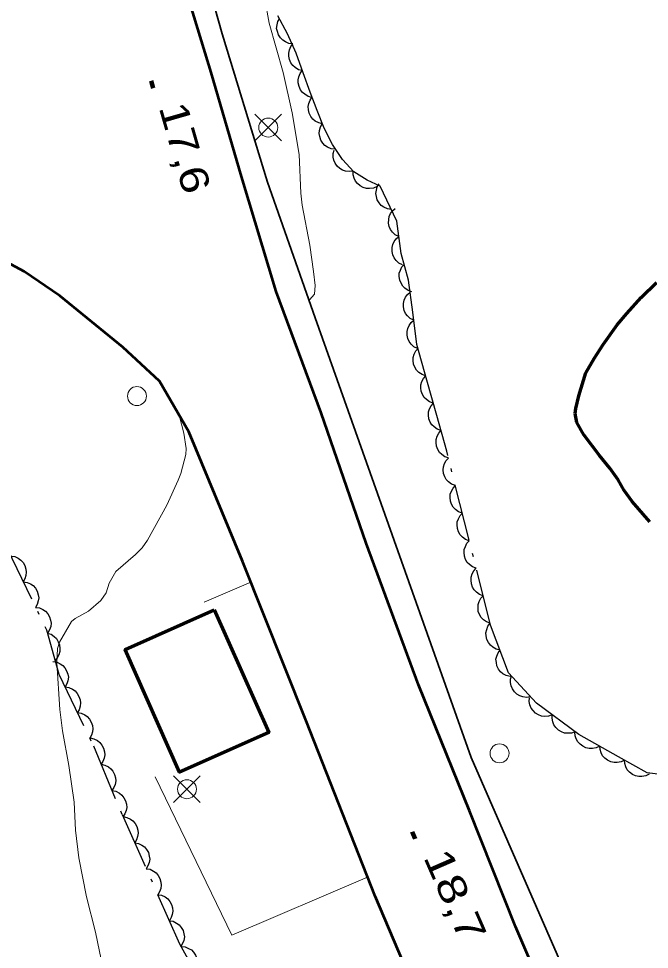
# Model space of a CAD drawing. Extents: x 355726 to 357533, y 5103782 to 5105258.
# Drawn here: x 356339.71 to 356372.99, y 5104791.53 to 5104840.63 of the extents above; entities that cross this region are included whole.
import ezdxf

# ---------------------------------------------------------------- set-up
doc = ezdxf.new("R2010")
doc.units = 0
doc.header["$LTSCALE"] = 0.6
doc.linetypes.add('DOT_DASHED', pattern=[7.7, 5, -1.2, 0.3, -1.2])
doc.linetypes.add('LONG_DASHED', pattern=[7.5, 6, -1.5])
for name, color, linetype, lineweight in [('19', 7, 'Continuous', 13), ('2', 7, 'LONG_DASHED', 13), ('21', 7, 'LONG_DASHED', 35), ('22', 7, 'Continuous', 13), ('3', 7, 'Continuous', 140), ('31', 7, 'Continuous', 35), ('36', 7, 'Continuous', 13), ('44', 7, 'Continuous', 25)]:
    doc.layers.add(name, color=color, linetype=linetype, lineweight=lineweight)

msp = doc.modelspace()

# ---------------------------------------------------------------- linework, layer by layer
at = {"layer": '19'}
msp.add_line((356351.97, 5104810.9), (356349.5, 5104809.84), dxfattribs=at)
msp.add_lwpolyline([(356346.92, 5104800.63), (356350.96, 5104792.28), (356358.13, 5104795.33)], dxfattribs=at)
at = {"layer": '2', "linetype": 'Continuous'}
for points in [[(356355.04, 5104825.77), (356355.07, 5104825.79), (356355.33, 5104826.09), (356355.37, 5104826.55), (356355.28, 5104827.3), (356355.08, 5104828.68), (356354.68, 5104830.8), (356354.6, 5104831.42), (356354.51, 5104833.46), (356354.14, 5104835.66), (356353.67, 5104837.8), (356352.94, 5104840.4), (356352.7, 5104841.67)], [(356344.33, 5104810.34), (356344.5, 5104810.84), (356344.85, 5104811.47), (356345.89, 5104812.36), (356346.23, 5104812.72), (356346.52, 5104813.12), (356347.54, 5104814.96), (356348.13, 5104816.28), (356348.27, 5104816.63), (356348.53, 5104817.63), (356348.56, 5104817.95), (356348.44, 5104818.76), (356348.19, 5104819.71)]]:
    msp.add_lwpolyline(points, dxfattribs=at)
at = {"layer": '2'}
msp.add_lwpolyline([(356344.17, 5104790.49), (356343.78, 5104792.43), (356343.29, 5104794.3), (356342.89, 5104796.36), (356342.72, 5104797.82), (356342.64, 5104799.29), (356342.37, 5104801.23), (356342.03, 5104803.05), (356341.89, 5104804.18), (356341.73, 5104806.65), (356341.77, 5104807.4), (356341.88, 5104807.74), (356342.5, 5104808.82), (356342.7, 5104808.98), (356343.41, 5104809.37), (356344.06, 5104809.93), (356344.33, 5104810.34)], dxfattribs=at)
at = {"layer": '21', "linetype": 'Continuous', "lineweight": 53}
for points in [[(356404.43, 5104711.57), (356400.53, 5104719.2), (356396.79, 5104726.53), (356393.27, 5104733.76), (356389.5, 5104741.82), (356385.15, 5104750.63), (356381.56, 5104758.3), (356377.92, 5104765.58), (356374.7, 5104772.49), (356371.83, 5104779.33), (356369.06, 5104785.41), (356365.93, 5104792.73), (356363.5, 5104798.84), (356360.81, 5104805.48), (356358.05, 5104812.95), (356355.68, 5104819.84), (356353.31, 5104826.24), (356351.48, 5104832.3), (356349.87, 5104837.8), (356347.69, 5104844.95), (356345.93, 5104851.12), (356344.93, 5104854.88), (356343.69, 5104859.4)], [(356399.2, 5104708.25), (356395.34, 5104715.51), (356391.68, 5104722.78), (356387.44, 5104731.3), (356383.54, 5104739.59), (356379.77, 5104747.55), (356376.2, 5104754.88), (356372.76, 5104762.24), (356368.76, 5104770.76), (356365.14, 5104778.76), (356362.28, 5104785.51), (356358.52, 5104794.34), (356354.89, 5104803.59), (356351.53, 5104812), (356348.69, 5104818.84), (356347.14, 5104821.51), (356345.22, 5104823.3), (356341.89, 5104826.01), (356340, 5104827.3), (356337.89, 5104828.42)]]:
    msp.add_lwpolyline(points, dxfattribs=at)
at = {"layer": '22', "lineweight": 35}
msp.add_lwpolyline([(356343.73, 5104859.46), (356345.26, 5104859.67), (356346.18, 5104855.37), (356348.16, 5104847.95), (356350.45, 5104839.83), (356352.85, 5104832.01), (356355.37, 5104824.84), (356363.6, 5104801.65), (356370.06, 5104786.82), (356377.26, 5104770.55), (356384.15, 5104755.63), (356392.22, 5104739.09), (356398.99, 5104725.29), (356406.44, 5104710.76)], dxfattribs=at)
at = {"layer": '22', "linetype": 'LONG_DASHED', "lineweight": 70}
msp.add_lwpolyline([(356373.02, 5104814.09), (356372.09, 5104815.15), (356371.66, 5104815.74), (356371.35, 5104816.3), (356370.91, 5104816.92), (356370.36, 5104817.59), (356369.53, 5104818.68), (356369.17, 5104819.33), (356369.08, 5104819.8), (356369.11, 5104820.07), (356369.27, 5104820.74), (356369.65, 5104821.95), (356370.08, 5104822.7), (356370.56, 5104823.44), (356371.3, 5104824.48), (356371.8, 5104825.08), (356372.57, 5104825.92), (356373.37, 5104826.72)], dxfattribs=at)
at = {"layer": '3'}
for p, q in [((356346.71, 5104837.35), (356346.82, 5104836.97)), ((356360.48, 5104797.72), (356360.64, 5104797.36))]:
    msp.add_line(p, q, dxfattribs=at)
at = {"layer": '31', "lineweight": 70}
msp.add_lwpolyline([(356350.03, 5104809.44), (356352.91, 5104802.97), (356348.21, 5104800.88), (356345.33, 5104807.34), (356350.03, 5104809.44)], close=True, dxfattribs=at)
at = {"layer": '36'}
for p, q in [((356353.59, 5104834.18), (356352.18, 5104835.59)), ((356352.18, 5104834.18), (356353.59, 5104835.59)), ((356349.3, 5104799.27), (356347.89, 5104800.68)), ((356347.89, 5104799.27), (356349.3, 5104800.68))]:
    msp.add_line(p, q, dxfattribs=at)
for centre in [(356352.887, 5104834.887), (356345.959, 5104820.72), (356365.089, 5104801.87), (356348.597, 5104799.977)]:
    msp.add_circle(centre, 0.5, dxfattribs=at)
at = {"layer": '44'}
for points in [[(356354.19, 5104839.31), (356353.98, 5104839.33), (356353.79, 5104839.41), (356353.65, 5104839.5), (356353.53, 5104839.62), (356353.43, 5104839.78), (356353.37, 5104839.96), (356353.33, 5104840.12), (356353.35, 5104840.3), (356353.4, 5104840.48), (356353.48, 5104840.63)], [(356354.68, 5104837.89), (356354.48, 5104837.94), (356354.31, 5104838.05), (356354.18, 5104838.16), (356354.08, 5104838.3), (356354.01, 5104838.47), (356353.97, 5104838.66), (356353.97, 5104838.82), (356354.01, 5104838.99), (356354.08, 5104839.16), (356354.19, 5104839.31)], [(356355.19, 5104836.48), (356354.99, 5104836.53), (356354.81, 5104836.64), (356354.69, 5104836.74), (356354.59, 5104836.88), (356354.51, 5104837.05), (356354.47, 5104837.24), (356354.46, 5104837.4), (356354.5, 5104837.57), (356354.57, 5104837.74), (356354.68, 5104837.89)], [(356355.75, 5104835.09), (356355.55, 5104835.13), (356355.37, 5104835.23), (356355.24, 5104835.33), (356355.13, 5104835.47), (356355.05, 5104835.64), (356355.01, 5104835.82), (356354.99, 5104835.99), (356355.03, 5104836.16), (356355.09, 5104836.33), (356355.19, 5104836.48)], [(356356.41, 5104833.74), (356356.2, 5104833.77), (356356.02, 5104833.85), (356355.88, 5104833.94), (356355.76, 5104834.07), (356355.66, 5104834.22), (356355.6, 5104834.41), (356355.57, 5104834.57), (356355.59, 5104834.74), (356355.64, 5104834.92), (356355.73, 5104835.08)], [(356357.37, 5104832.59), (356357.17, 5104832.56), (356356.96, 5104832.59), (356356.81, 5104832.63), (356356.66, 5104832.73), (356356.52, 5104832.85), (356356.42, 5104833.01), (356356.34, 5104833.16), (356356.31, 5104833.33), (356356.31, 5104833.52), (356356.36, 5104833.69)], [(356358.63, 5104831.77), (356358.44, 5104831.69), (356358.23, 5104831.67), (356358.07, 5104831.67), (356357.9, 5104831.72), (356357.74, 5104831.81), (356357.6, 5104831.94), (356357.49, 5104832.06), (356357.42, 5104832.22), (356357.37, 5104832.4), (356357.36, 5104832.58)], [(356359.38, 5104830.56), (356359.17, 5104830.59), (356358.99, 5104830.68), (356358.85, 5104830.77), (356358.74, 5104830.91), (356358.64, 5104831.07), (356358.59, 5104831.25), (356358.56, 5104831.41), (356358.59, 5104831.59), (356358.64, 5104831.76), (356358.73, 5104831.92)], [(356359.78, 5104829.14), (356359.59, 5104829.23), (356359.44, 5104829.37), (356359.34, 5104829.5), (356359.27, 5104829.66), (356359.23, 5104829.84), (356359.24, 5104830.03), (356359.26, 5104830.19), (356359.34, 5104830.35), (356359.45, 5104830.5), (356359.58, 5104830.62)], [(356359.97, 5104827.65), (356359.78, 5104827.74), (356359.63, 5104827.88), (356359.53, 5104828.01), (356359.46, 5104828.17), (356359.42, 5104828.35), (356359.43, 5104828.55), (356359.46, 5104828.71), (356359.53, 5104828.87), (356359.64, 5104829.02), (356359.78, 5104829.14)], [(356360.47, 5104826.22), (356360.27, 5104826.29), (356360.1, 5104826.41), (356359.98, 5104826.52), (356359.89, 5104826.67), (356359.82, 5104826.84), (356359.8, 5104827.03), (356359.8, 5104827.2), (356359.86, 5104827.36), (356359.94, 5104827.53), (356360.06, 5104827.67)], [(356360.56, 5104824.72), (356360.38, 5104824.81), (356360.23, 5104824.95), (356360.13, 5104825.08), (356360.06, 5104825.24), (356360.02, 5104825.42), (356360.03, 5104825.61), (356360.05, 5104825.78), (356360.13, 5104825.93), (356360.24, 5104826.08), (356360.37, 5104826.2)], [(356360.76, 5104823.23), (356360.57, 5104823.32), (356360.42, 5104823.46), (356360.32, 5104823.59), (356360.25, 5104823.75), (356360.21, 5104823.93), (356360.22, 5104824.13), (356360.25, 5104824.29), (356360.32, 5104824.45), (356360.43, 5104824.6), (356360.56, 5104824.72)], [(356361.19, 5104821.79), (356361, 5104821.86), (356360.83, 5104821.97), (356360.71, 5104822.09), (356360.62, 5104822.24), (356360.55, 5104822.41), (356360.53, 5104822.6), (356360.53, 5104822.76), (356360.59, 5104822.93), (356360.67, 5104823.1), (356360.79, 5104823.23)], [(356361.6, 5104820.35), (356361.4, 5104820.41), (356361.23, 5104820.53), (356361.11, 5104820.64), (356361.02, 5104820.8), (356360.96, 5104820.97), (356360.94, 5104821.16), (356360.94, 5104821.32), (356360.99, 5104821.49), (356361.08, 5104821.65), (356361.2, 5104821.79)], [(356362, 5104818.9), (356361.8, 5104818.97), (356361.64, 5104819.09), (356361.52, 5104819.2), (356361.43, 5104819.35), (356361.36, 5104819.52), (356361.34, 5104819.71), (356361.34, 5104819.88), (356361.4, 5104820.04), (356361.48, 5104820.21), (356361.6, 5104820.35)], [(356362.4, 5104817.46), (356362.2, 5104817.52), (356362.04, 5104817.64), (356361.92, 5104817.75), (356361.83, 5104817.9), (356361.76, 5104818.08), (356361.74, 5104818.27), (356361.74, 5104818.43), (356361.8, 5104818.6), (356361.88, 5104818.76), (356362, 5104818.9)], [(356362.76, 5104816), (356362.56, 5104816.07), (356362.4, 5104816.19), (356362.28, 5104816.31), (356362.2, 5104816.46), (356362.14, 5104816.64), (356362.12, 5104816.83), (356362.13, 5104816.99), (356362.18, 5104817.16), (356362.27, 5104817.32), (356362.39, 5104817.45)], [(356363.13, 5104814.54), (356362.93, 5104814.62), (356362.77, 5104814.74), (356362.65, 5104814.85), (356362.56, 5104815.01), (356362.5, 5104815.18), (356362.49, 5104815.37), (356362.49, 5104815.54), (356362.55, 5104815.7), (356362.64, 5104815.86), (356362.76, 5104816)], [(356363.49, 5104813.09), (356363.3, 5104813.16), (356363.13, 5104813.28), (356363.02, 5104813.4), (356362.93, 5104813.55), (356362.87, 5104813.73), (356362.86, 5104813.92), (356362.86, 5104814.08), (356362.92, 5104814.25), (356363.01, 5104814.41), (356363.13, 5104814.54)], [(356363.86, 5104811.64), (356363.66, 5104811.71), (356363.5, 5104811.83), (356363.38, 5104811.94), (356363.3, 5104812.1), (356363.24, 5104812.27), (356363.22, 5104812.46), (356363.23, 5104812.63), (356363.29, 5104812.79), (356363.37, 5104812.96), (356363.49, 5104813.09)], [(356339.3, 5104812.28), (356339.51, 5104812.25), (356339.7, 5104812.16), (356339.83, 5104812.07), (356339.95, 5104811.94), (356340.04, 5104811.78), (356340.1, 5104811.59), (356340.12, 5104811.43), (356340.1, 5104811.26), (356340.05, 5104811.08), (356339.96, 5104810.92)], [(356364.23, 5104810.18), (356364.03, 5104810.25), (356363.87, 5104810.37), (356363.75, 5104810.49), (356363.67, 5104810.64), (356363.61, 5104810.82), (356363.59, 5104811.01), (356363.59, 5104811.17), (356363.65, 5104811.34), (356363.74, 5104811.5), (356363.86, 5104811.64)], [(356339.96, 5104810.92), (356340.16, 5104810.89), (356340.35, 5104810.81), (356340.49, 5104810.72), (356340.6, 5104810.58), (356340.69, 5104810.43), (356340.75, 5104810.24), (356340.78, 5104810.08), (356340.75, 5104809.91), (356340.7, 5104809.73), (356340.61, 5104809.57)], [(356364.6, 5104808.73), (356364.4, 5104808.8), (356364.24, 5104808.92), (356364.12, 5104809.04), (356364.03, 5104809.19), (356363.97, 5104809.36), (356363.96, 5104809.56), (356363.96, 5104809.72), (356364.02, 5104809.88), (356364.11, 5104810.05), (356364.23, 5104810.18)], [(356340.61, 5104809.57), (356340.82, 5104809.54), (356341, 5104809.46), (356341.14, 5104809.37), (356341.25, 5104809.23), (356341.35, 5104809.08), (356341.4, 5104808.89), (356341.43, 5104808.73), (356341.41, 5104808.56), (356341.35, 5104808.38), (356341.26, 5104808.22)], [(356365.12, 5104807.32), (356364.91, 5104807.37), (356364.74, 5104807.47), (356364.61, 5104807.57), (356364.5, 5104807.72), (356364.42, 5104807.88), (356364.39, 5104808.07), (356364.37, 5104808.23), (356364.41, 5104808.4), (356364.48, 5104808.58), (356364.58, 5104808.72)], [(356341.23, 5104808.21), (356341.43, 5104808.15), (356341.59, 5104808.03), (356341.72, 5104807.92), (356341.81, 5104807.76), (356341.87, 5104807.59), (356341.89, 5104807.4), (356341.89, 5104807.24), (356341.84, 5104807.07), (356341.75, 5104806.91), (356341.64, 5104806.77)], [(356365.65, 5104805.92), (356365.44, 5104805.97), (356365.27, 5104806.07), (356365.14, 5104806.17), (356365.03, 5104806.31), (356364.95, 5104806.48), (356364.92, 5104806.67), (356364.9, 5104806.83), (356364.94, 5104807), (356365.01, 5104807.17), (356365.12, 5104807.32)], [(356341.52, 5104806.72), (356341.72, 5104806.69), (356341.91, 5104806.6), (356342.05, 5104806.51), (356342.16, 5104806.38), (356342.25, 5104806.22), (356342.31, 5104806.04), (356342.34, 5104805.88), (356342.31, 5104805.7), (356342.26, 5104805.53), (356342.17, 5104805.37)], [(356366.73, 5104804.85), (356366.52, 5104804.82), (356366.32, 5104804.85), (356366.16, 5104804.9), (356366.01, 5104804.99), (356365.88, 5104805.12), (356365.77, 5104805.28), (356365.7, 5104805.43), (356365.67, 5104805.6), (356365.67, 5104805.79), (356365.72, 5104805.96)], [(356342.17, 5104805.37), (356342.37, 5104805.34), (356342.56, 5104805.25), (356342.7, 5104805.16), (356342.81, 5104805.03), (356342.9, 5104804.87), (356342.96, 5104804.69), (356342.98, 5104804.53), (356342.96, 5104804.35), (356342.91, 5104804.17), (356342.82, 5104804.02)], [(356367.87, 5104803.9), (356367.68, 5104803.83), (356367.47, 5104803.82), (356367.31, 5104803.83), (356367.15, 5104803.9), (356366.99, 5104803.99), (356366.86, 5104804.13), (356366.75, 5104804.26), (356366.69, 5104804.42), (356366.66, 5104804.61), (356366.67, 5104804.79)], [(356342.82, 5104804.02), (356343.02, 5104803.99), (356343.21, 5104803.9), (356343.34, 5104803.81), (356343.46, 5104803.68), (356343.55, 5104803.52), (356343.61, 5104803.33), (356343.63, 5104803.17), (356343.61, 5104803), (356343.56, 5104802.82), (356343.47, 5104802.67)], [(356369.08, 5104803.01), (356368.89, 5104802.94), (356368.68, 5104802.93), (356368.52, 5104802.94), (356368.35, 5104803.01), (356368.2, 5104803.1), (356368.06, 5104803.24), (356367.96, 5104803.37), (356367.9, 5104803.53), (356367.87, 5104803.72), (356367.87, 5104803.9)], [(356370.38, 5104802.25), (356370.19, 5104802.16), (356369.99, 5104802.12), (356369.82, 5104802.12), (356369.65, 5104802.16), (356369.48, 5104802.24), (356369.34, 5104802.36), (356369.22, 5104802.47), (356369.14, 5104802.63), (356369.08, 5104802.8), (356369.07, 5104802.98)], [(356343.49, 5104802.68), (356343.69, 5104802.63), (356343.87, 5104802.54), (356344, 5104802.44), (356344.11, 5104802.3), (356344.2, 5104802.14), (356344.24, 5104801.95), (356344.26, 5104801.79), (356344.23, 5104801.62), (356344.16, 5104801.44), (356344.07, 5104801.29)], [(356371.68, 5104801.51), (356371.5, 5104801.42), (356371.3, 5104801.39), (356371.13, 5104801.38), (356370.96, 5104801.42), (356370.79, 5104801.5), (356370.64, 5104801.62), (356370.53, 5104801.74), (356370.45, 5104801.89), (356370.39, 5104802.07), (356370.38, 5104802.25)], [(356372.99, 5104800.77), (356372.8, 5104800.68), (356372.6, 5104800.65), (356372.43, 5104800.64), (356372.26, 5104800.69), (356372.1, 5104800.76), (356371.95, 5104800.88), (356371.83, 5104801), (356371.75, 5104801.16), (356371.7, 5104801.33), (356371.68, 5104801.51)], [(356344.07, 5104801.29), (356344.27, 5104801.25), (356344.45, 5104801.15), (356344.58, 5104801.06), (356344.69, 5104800.92), (356344.78, 5104800.75), (356344.82, 5104800.57), (356344.84, 5104800.41), (356344.81, 5104800.23), (356344.74, 5104800.06), (356344.64, 5104799.91)], [(356344.64, 5104799.91), (356344.85, 5104799.87), (356345.03, 5104799.77), (356345.16, 5104799.67), (356345.27, 5104799.53), (356345.35, 5104799.37), (356345.4, 5104799.18), (356345.42, 5104799.02), (356345.39, 5104798.85), (356345.32, 5104798.67), (356345.22, 5104798.52)], [(356345.23, 5104798.53), (356345.43, 5104798.49), (356345.61, 5104798.4), (356345.75, 5104798.3), (356345.86, 5104798.17), (356345.95, 5104798), (356346, 5104797.82), (356346.02, 5104797.66), (356345.99, 5104797.48), (356345.93, 5104797.31), (356345.84, 5104797.15)], [(356345.84, 5104797.15), (356346.04, 5104797.12), (356346.22, 5104797.03), (356346.36, 5104796.93), (356346.47, 5104796.79), (356346.56, 5104796.63), (356346.61, 5104796.45), (356346.63, 5104796.29), (356346.6, 5104796.11), (356346.54, 5104795.94), (356346.45, 5104795.78)], [(356346.45, 5104795.78), (356346.65, 5104795.75), (356346.83, 5104795.66), (356346.97, 5104795.56), (356347.08, 5104795.42), (356347.17, 5104795.26), (356347.22, 5104795.08), (356347.24, 5104794.92), (356347.21, 5104794.74), (356347.15, 5104794.57), (356347.06, 5104794.41)], [(356347.06, 5104794.41), (356347.26, 5104794.38), (356347.44, 5104794.29), (356347.58, 5104794.19), (356347.69, 5104794.05), (356347.78, 5104793.89), (356347.83, 5104793.71), (356347.85, 5104793.55), (356347.82, 5104793.37), (356347.76, 5104793.2), (356347.67, 5104793.04)], [(356347.67, 5104793.04), (356347.87, 5104793.01), (356348.05, 5104792.91), (356348.19, 5104792.82), (356348.3, 5104792.68), (356348.39, 5104792.52), (356348.44, 5104792.34), (356348.46, 5104792.18), (356348.43, 5104792), (356348.37, 5104791.83), (356348.28, 5104791.67)], [(356348.29, 5104791.68), (356348.5, 5104791.66), (356348.68, 5104791.58), (356348.83, 5104791.5), (356348.95, 5104791.37), (356349.05, 5104791.22), (356349.11, 5104791.04), (356349.15, 5104790.88), (356349.13, 5104790.7), (356349.09, 5104790.52), (356349.01, 5104790.36)]]:
    msp.add_lwpolyline(points, dxfattribs=at)
at = {"layer": '44', "linetype": 'DOT_DASHED'}
for points in [[(356374.71, 5104800.6), (356372.87, 5104800.84), (356371.37, 5104801.69), (356369.27, 5104802.87), (356367.04, 5104804.51), (356365.57, 5104806.12), (356364.62, 5104808.63), (356362.3, 5104817.82), (356361.78, 5104819.69), (356361.26, 5104821.56), (356360.73, 5104823.44), (356360.51, 5104825.14), (356360.29, 5104826.84), (356359.89, 5104828.25), (356359.67, 5104829.95), (356358.79, 5104831.8), (356358.1, 5104832.11), (356357.41, 5104832.55), (356356.81, 5104833.2), (356356.28, 5104834), (356355.84, 5104834.86), (356355.47, 5104835.79), (356355.09, 5104836.76), (356354.72, 5104837.78), (356354.36, 5104838.82), (356353.91, 5104839.83), (356353.4, 5104840.79)], [(356339.09, 5104812.72), (356341.18, 5104808.39), (356341.84, 5104806.05), (356343.66, 5104802.26), (356345.17, 5104798.65), (356348.21, 5104791.82), (356349.77, 5104788.97), (356351.88, 5104785.02), (356356.16, 5104777.88), (356358.01, 5104774.87), (356361.29, 5104769.48), (356363.28, 5104765.99), (356366.48, 5104759.07), (356368.3, 5104755.28), (356370.24, 5104751.03), (356371.5, 5104748.36), (356373.88, 5104743.47), (356375.99, 5104739.52), (356378.07, 5104734.8), (356379.46, 5104731.66), (356382.83, 5104725.03), (356385.47, 5104719.21), (356387.88, 5104715.09)]]:
    msp.add_lwpolyline(points, dxfattribs=at)

# ---------------------------------------------------------------- texts
at = {"layer": '3'}
for s, rotation, width, p in [('17,6   ', 286.023, 1.25, (356347.1, 5104835.96)), ('18,7   ', 293.537, 1.3, (356361.05, 5104796.4))]:
    msp.add_text(s, height=1.5, rotation=rotation, dxfattribs=dict(at, width=width)).set_placement(p)

doc.saveas('drawing.dxf')
